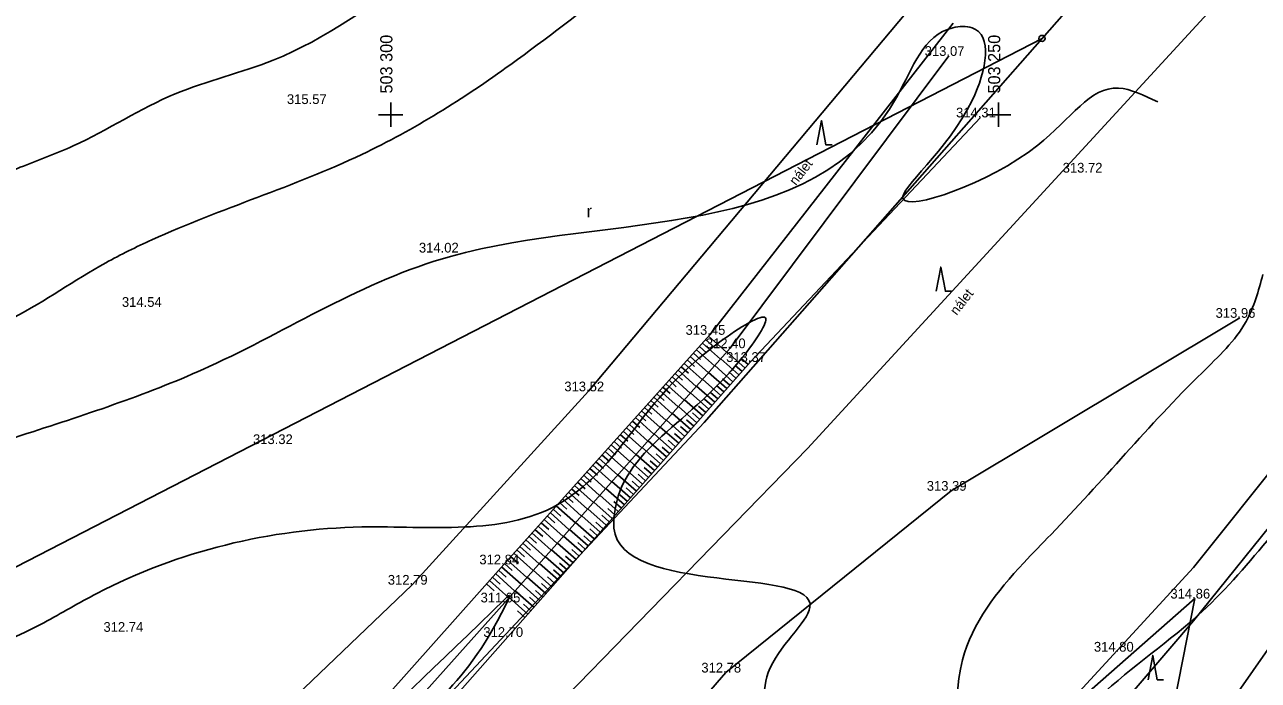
# Model space of a CAD drawing. Extents: x -504375 to -503125, y -1118000 to -1116474.
# Drawn here: x -503330.1 to -503228.6, y -1116596.5 to -1116542.6 of the extents above; entities that cross this region are included whole.
import ezdxf

# ---------------------------------------------------------------- set-up
doc = ezdxf.new("R2010")
doc.units = 0
for name, color, linetype in [('Druhy povrchů', 7, 'Continuous'), ('Podkladové mapy', 7, 'Continuous'), ('Vodní plochy', 7, 'Continuous'), ('Vrstva 34', 7, 'Continuous'), ('Vrstva 48', 7, 'Continuous'), ('Výškopis', 7, 'Continuous'), ('Výšky bodů plotr', 7, 'Continuous')]:
    doc.layers.add(name, color=color, linetype=linetype)

msp = doc.modelspace()

# ---------------------------------------------------------------- linework, layer by layer
at = {"layer": 'Druhy povrchů'}
for points in [[(-503397.02, -1116689.72), (-503380.03, -1116674.83), (-503363.8, -1116660.36), (-503349.88, -1116645.16), (-503336.27, -1116629.65), (-503324.3, -1116612.68), (-503313.46, -1116603.24), (-503298.24, -1116588.67), (-503283.72, -1116572.76), (-503255.76, -1116539.4)], [(-503264.953, -1116552.481), (-503264.578, -1116550.481), (-503264.203, -1116552.481), (-503263.703, -1116552.481)], [(-503255.127, -1116564.531), (-503254.752, -1116562.531), (-503254.377, -1116564.531), (-503253.877, -1116564.531)], [(-503585.68, -1116948.36), (-503569.03, -1116928.88), (-503555.79, -1116911.97), (-503526.22, -1116880.66), (-503498.19, -1116855.24), (-503492.29, -1116850.5), (-503465.52, -1116813.76), (-503435.92, -1116779.91), (-503416.58, -1116756.7), (-503397.18, -1116739.15), (-503383.4, -1116725.23), (-503367.95, -1116706.66), (-503351.89, -1116693.92), (-503339.03, -1116678.06), (-503323.29, -1116660.89), (-503310.81, -1116645.12), (-503295.5, -1116628.53), (-503285, -1116610.41), (-503272.45, -1116595.9), (-503253.91, -1116580.94), (-503230.15, -1116566.71)], [(-503237.698, -1116596.494), (-503237.323, -1116594.494), (-503236.948, -1116596.494), (-503236.448, -1116596.494)]]:
    msp.add_lwpolyline(points, dxfattribs=at)
at = {"layer": 'Podkladové mapy'}
for p, q in [((-503246.43, -1116543.72), (-503238.29, -1116534.46)), ((-503265.72, -1116577.46), (-503230.27, -1116538.88)), ((-503246.43, -1116543.72), (-503274.22, -1116575.33)), ((-503233.98, -1116587.25), (-503210.38, -1116557.71)), ((-503207.06, -1116558.21), (-503233.96, -1116591.65)), ((-503274.22, -1116575.33), (-503314.42, -1116618.21)), ((-503307.65, -1116620.55), (-503265.72, -1116577.46)), ((-503276.78, -1116633.82), (-503233.98, -1116587.25)), ((-503233.96, -1116591.65), (-503250.83, -1116611.29))]:
    msp.add_line(p, q, dxfattribs=at)
msp.add_lwpolyline([(-503572.98, -1116711.95), (-503406.03, -1116625.94), (-503246.43, -1116543.72)], dxfattribs=at)
for radius in [0.25, 0.005]:
    msp.add_circle((-503246.43, -1116543.72), radius, dxfattribs=at)
at = {"layer": 'Vodní plochy'}
for points in [[(-503272.08, -1116569.21), (-503254.08, -1116545.16)], [(-503290.61, -1116590.13), (-503272.08, -1116569.21)], [(-503334.47, -1116638.19), (-503314.17, -1116616.49), (-503290.61, -1116590.13)]]:
    msp.add_lwpolyline(points, dxfattribs=at)
at = {"layer": 'Vrstva 34'}
for p, q in [((-503300, -1116549), (-503300, -1116551)), ((-503250, -1116549), (-503250, -1116551)), ((-503299, -1116550), (-503301, -1116550)), ((-503249, -1116550), (-503251, -1116550))]:
    msp.add_line(p, q, dxfattribs=at)
at = {"layer": 'Vrstva 48'}
msp.add_lwpolyline([(-503300.434, -1116681.166), (-503296.556, -1116668.103), (-503294.8, -1116667.049), (-503286.048, -1116656.931), (-503285.304, -1116656.071), (-503279.91, -1116655.384), (-503275.719, -1116650.391), (-503271.777, -1116639.009), (-503265.04, -1116633.168), (-503262.143, -1116630.656), (-503250.15, -1116616.106), (-503234.98, -1116601.014), (-503231.273, -1116598.925), (-503211.098, -1116569.991), (-503210.256, -1116567.168)], dxfattribs=at)
for points in [[(-503290.496, -1116506.883), (-503309.393, -1116518.46), (-503328.29, -1116524.624), (-503350.268, -1116534.452), (-503366.085, -1116542.864), (-503383.317, -1116553.192), (-503389.867, -1116555.566), (-503411.101, -1116563.377)], [(-503423.262, -1116584.1), (-503400.51, -1116574.995), (-503371.603, -1116564.462), (-503355.454, -1116554.107), (-503339.126, -1116544.288), (-503329.669, -1116539.646), (-503315.72, -1116535.868), (-503281.172, -1116514.546)], [(-503272.713, -1116521.984), (-503284.552, -1116530.049), (-503297.613, -1116538.288), (-503309.659, -1116545.506), (-503317.719, -1116548.279), (-503326.116, -1116552.563), (-503330.483, -1116554.327), (-503334.009, -1116555.839), (-503347.343, -1116563.628), (-503356.881, -1116570.175), (-503363.037, -1116574.013), (-503376.976, -1116580.659), (-503385.521, -1116583.565), (-503391.321, -1116585.975), (-503395.157, -1116587.671), (-503409.879, -1116592.332), (-503411.663, -1116592.332), (-503418.533, -1116597.758), (-503431.06, -1116606.789)], [(-503388.833, -1116595.439), (-503375.375, -1116590.932), (-503361.776, -1116585.15), (-503355.232, -1116582.174), (-503340.443, -1116571.289), (-503331.009, -1116566.697), (-503323.444, -1116562.19), (-503319.644, -1116560.289), (-503302.365, -1116553.261), (-503290.126, -1116545.863), (-503272.293, -1116533.997), (-503262.721, -1116530.889)], [(-503465.065, -1116647.979), (-503454.005, -1116643.254), (-503444.995, -1116644.684), (-503441.273, -1116642.635), (-503427.473, -1116633.37), (-503425.422, -1116628.769), (-503418.525, -1116619.631), (-503414.99, -1116617.273), (-503410.82, -1116614.036), (-503399.7, -1116608.038), (-503368.713, -1116598.755), (-503365.041, -1116596.617), (-503349.145, -1116588.639), (-503333.919, -1116577.69), (-503329.925, -1116576.242), (-503314.946, -1116570.728), (-503295.077, -1116561.657), (-503258.316, -1116548.433), (-503253.777, -1116542.843), (-503252.181, -1116542.843), (-503252.181, -1116548.832), (-503257.867, -1116556.916), (-503246.784, -1116552.513), (-503240.14, -1116547.809), (-503236.915, -1116548.947)], [(-503228.261, -1116563.145), (-503229.645, -1116567.016), (-503233.265, -1116571.228), (-503245.688, -1116584.541), (-503247.935, -1116586.867), (-503252.973, -1116594.854), (-503254.135, -1116607.338), (-503261.55, -1116616.428), (-503262.857, -1116617.898), (-503273.652, -1116628.941), (-503288.12, -1116641.769), (-503294.834, -1116647.413), (-503299.542, -1116653.756), (-503302.433, -1116657.068), (-503311.897, -1116663.915), (-503313.227, -1116667.667), (-503316.736, -1116674.505), (-503325.627, -1116690.3), (-503328.511, -1116695.009), (-503335.94, -1116707.278), (-503351.034, -1116723.382), (-503365.126, -1116737.245), (-503372.674, -1116748.782), (-503373.925, -1116753.16), (-503378.551, -1116760.666), (-503382.552, -1116767.547), (-503390.579, -1116780.739), (-503398.79, -1116793.818), (-503400.908, -1116797.881), (-503402.495, -1116807.226), (-503404.198, -1116812.046), (-503412.471, -1116822.312), (-503418.387, -1116829.995), (-503420.024, -1116835.788), (-503425.814, -1116843.155), (-503430.336, -1116857.921), (-503433.683, -1116863.223), (-503434.674, -1116865.019), (-503440.926, -1116880.75), (-503445.259, -1116893.88)], [(-503481.504, -1116663.518), (-503468.547, -1116657.036), (-503463.489, -1116655.349), (-503455.413, -1116652.508), (-503447.337, -1116652.508), (-503443.352, -1116653.982), (-503430.298, -1116650.555), (-503416.187, -1116635.106), (-503410.685, -1116628.713), (-503402.504, -1116619.064), (-503381.737, -1116613.158), (-503370.807, -1116610.971), (-503361.189, -1116605.649), (-503353.61, -1116601.494), (-503341.223, -1116596.974), (-503328.544, -1116591.798), (-503324.172, -1116589.392), (-503302.385, -1116583.924), (-503293.932, -1116583.924), (-503286.266, -1116582.08), (-503284.637, -1116580.965), (-503272.933, -1116568.697), (-503269.17, -1116566.723), (-503271.089, -1116569.984), (-503281.636, -1116583.324), (-503281.636, -1116584.01), (-503265.516, -1116590.53), (-503268.945, -1116595.892), (-503268.945, -1116601.682), (-503275.976, -1116612.148), (-503282.064, -1116615.751), (-503283.352, -1116619.8), (-503288.876, -1116631.779), (-503303.377, -1116644.015), (-503307.12, -1116648.093), (-503316.743, -1116659.793), (-503321.087, -1116663.538), (-503326.965, -1116676.097), (-503331.52, -1116684.914), (-503334.134, -1116690.218), (-503342.049, -1116704.413), (-503355.564, -1116718.999), (-503373.009, -1116735.836), (-503382.317, -1116749.959), (-503386.693, -1116758.655), (-503400.779, -1116777.303), (-503409.619, -1116795.183), (-503415, -1116808.93), (-503418.611, -1116811.169), (-503424.106, -1116823.61), (-503426.69, -1116826.983), (-503429.797, -1116836.064), (-503433.946, -1116846.027), (-503439.043, -1116851.839), (-503444.852, -1116860.972), (-503445.916, -1116865.085), (-503449.799, -1116874.02), (-503458.366, -1116891.656), (-503466.054, -1116907.093), (-503467.087, -1116909.659), (-503470.52, -1116921.657)], [(-503220.996, -1116567.416), (-503217.756, -1116573.319), (-503221.427, -1116577.942), (-503233.269, -1116590.886), (-503241.732, -1116597.917), (-503258.62, -1116620.268), (-503262.643, -1116624.456), (-503264.199, -1116625.94)], [(-503500.793, -1116684.248), (-503495.441, -1116680.588), (-503477.217, -1116668.929), (-503469.765, -1116665.54), (-503456.961, -1116660.999), (-503454.929, -1116660.999), (-503445.173, -1116663.507), (-503440.16, -1116663.507), (-503423.051, -1116661.635), (-503408.15, -1116643.863), (-503398.378, -1116637.057), (-503392.648, -1116629.281), (-503371.711, -1116623.281), (-503344.722, -1116616.898), (-503335.508, -1116616.898), (-503327.111, -1116617.444), (-503318.26, -1116618.008), (-503315.381, -1116615.168), (-503290.617, -1116589.867), (-503290.243, -1116589.549), (-503290.538, -1116590.342), (-503300.683, -1116602.384), (-503312.519, -1116617.365), (-503317.698, -1116623.075), (-503317.198, -1116634.398), (-503334.088, -1116662.805), (-503335.757, -1116674.673), (-503338.13, -1116679.069), (-503344.017, -1116691.861), (-503347.356, -1116698.983), (-503360.449, -1116714.28), (-503364.755, -1116720.083), (-503377.404, -1116731.328), (-503383.122, -1116736.828), (-503390.673, -1116749.224), (-503402.769, -1116767.78), (-503415.526, -1116779.825), (-503422.011, -1116793.522), (-503432.295, -1116810.757), (-503433.452, -1116814.845), (-503436.422, -1116824.389), (-503442.016, -1116838.148), (-503445.44, -1116842.843), (-503455.651, -1116858.198), (-503457.49, -1116865.559), (-503458.811, -1116869.597), (-503464.787, -1116881.025), (-503469.417, -1116887.701), (-503473.366, -1116895.33), (-503475.204, -1116901.869), (-503476.43, -1116909.702), (-503479.902, -1116915.22), (-503480.991, -1116921.623), (-503488.414, -1116937.171)]]:
    msp.add_spline(points, degree=3, dxfattribs=at)
at = {"layer": 'Výškopis'}
for p, q in [((-503274.606, -1116569.064), (-503274.015, -1116569.595)), ((-503274.356, -1116568.785), (-503272.878, -1116570.111)), ((-503274.105, -1116568.506), (-503273.515, -1116569.036)), ((-503273.855, -1116568.227), (-503272.381, -1116569.55)), ((-503275.358, -1116569.901), (-503273.873, -1116571.234)), ((-503275.107, -1116569.622), (-503274.514, -1116570.154)), ((-503274.857, -1116569.343), (-503273.376, -1116570.673)), ((-503271.354, -1116571.409), (-503272.855, -1116570.085)), ((-503270.857, -1116570.847), (-503272.357, -1116569.523)), ((-503270.609, -1116570.566), (-503271.209, -1116570.036)), ((-503276.36, -1116571.017), (-503274.867, -1116572.357)), ((-503276.109, -1116570.738), (-503275.513, -1116571.273)), ((-503275.859, -1116570.459), (-503274.37, -1116571.795)), ((-503275.608, -1116570.18), (-503275.014, -1116570.714)), ((-503271.85, -1116571.972), (-503273.352, -1116570.646)), ((-503271.105, -1116571.128), (-503271.706, -1116570.599)), ((-503277.362, -1116572.133), (-503275.862, -1116573.48)), ((-503277.111, -1116571.854), (-503276.512, -1116572.392)), ((-503276.861, -1116571.575), (-503275.365, -1116572.918)), ((-503276.61, -1116571.296), (-503276.013, -1116571.833)), ((-503272.842, -1116573.096), (-503274.347, -1116571.769)), ((-503272.346, -1116572.534), (-503273.849, -1116571.207)), ((-503272.098, -1116572.253), (-503272.699, -1116571.722)), ((-503271.602, -1116571.69), (-503272.202, -1116571.16)), ((-503278.114, -1116572.97), (-503277.511, -1116573.511)), ((-503277.863, -1116572.691), (-503276.359, -1116574.041)), ((-503277.613, -1116572.412), (-503277.012, -1116572.951)), ((-503273.835, -1116574.221), (-503275.341, -1116572.892)), ((-503273.339, -1116573.659), (-503274.844, -1116572.33)), ((-503273.09, -1116573.378), (-503273.692, -1116572.846)), ((-503272.594, -1116572.815), (-503273.196, -1116572.284)), ((-503279.116, -1116574.086), (-503278.51, -1116574.63)), ((-503278.865, -1116573.807), (-503277.354, -1116575.164)), ((-503278.615, -1116573.528), (-503278.011, -1116574.07)), ((-503278.364, -1116573.249), (-503276.856, -1116574.603)), ((-503274.827, -1116575.346), (-503276.336, -1116574.015)), ((-503274.331, -1116574.783), (-503275.838, -1116573.453)), ((-503274.083, -1116574.502), (-503274.686, -1116573.97)), ((-503273.587, -1116573.94), (-503274.189, -1116573.408)), ((-503280.118, -1116575.202), (-503279.509, -1116575.748)), ((-503279.867, -1116574.923), (-503278.348, -1116576.287)), ((-503279.617, -1116574.644), (-503279.01, -1116575.189)), ((-503279.366, -1116574.365), (-503277.851, -1116575.726)), ((-503275.82, -1116576.47), (-503277.33, -1116575.138)), ((-503275.324, -1116575.908), (-503276.833, -1116574.576)), ((-503275.075, -1116575.627), (-503275.679, -1116575.094)), ((-503274.579, -1116575.065), (-503275.182, -1116574.532)), ((-503280.869, -1116576.04), (-503279.343, -1116577.41)), ((-503280.619, -1116575.76), (-503280.009, -1116576.308)), ((-503280.368, -1116575.481), (-503278.846, -1116576.848)), ((-503276.316, -1116577.033), (-503277.827, -1116575.699)), ((-503276.068, -1116576.752), (-503276.672, -1116576.218)), ((-503275.572, -1116576.189), (-503276.176, -1116575.656)), ((-503281.871, -1116577.156), (-503280.338, -1116578.533)), ((-503281.621, -1116576.877), (-503281.008, -1116577.427)), ((-503281.37, -1116576.598), (-503279.841, -1116577.972)), ((-503281.12, -1116576.319), (-503280.509, -1116576.867)), ((-503277.309, -1116578.157), (-503278.822, -1116576.822)), ((-503276.812, -1116577.595), (-503278.325, -1116576.261)), ((-503276.564, -1116577.314), (-503277.169, -1116576.78)), ((-503282.623, -1116577.993), (-503282.007, -1116578.546)), ((-503282.373, -1116577.714), (-503280.835, -1116579.094)), ((-503282.122, -1116577.435), (-503281.508, -1116577.986)), ((-503278.301, -1116579.282), (-503279.817, -1116577.945)), ((-503277.805, -1116578.72), (-503279.319, -1116577.383)), ((-503277.557, -1116578.439), (-503278.162, -1116577.904)), ((-503277.06, -1116577.876), (-503277.666, -1116577.342)), ((-503283.625, -1116579.109), (-503283.006, -1116579.664)), ((-503283.375, -1116578.83), (-503281.83, -1116580.217)), ((-503283.124, -1116578.551), (-503282.507, -1116579.105)), ((-503282.874, -1116578.272), (-503281.332, -1116579.656)), ((-503279.294, -1116580.407), (-503280.811, -1116579.067)), ((-503278.797, -1116579.845), (-503280.314, -1116578.506)), ((-503278.549, -1116579.563), (-503279.156, -1116579.028)), ((-503278.053, -1116579.001), (-503278.659, -1116578.466)), ((-503284.627, -1116580.225), (-503284.006, -1116580.783)), ((-503284.377, -1116579.946), (-503282.824, -1116581.34)), ((-503284.126, -1116579.667), (-503283.506, -1116580.224)), ((-503283.876, -1116579.388), (-503282.327, -1116580.778)), ((-503280.286, -1116581.532), (-503281.806, -1116580.19)), ((-503279.79, -1116580.969), (-503281.309, -1116579.629)), ((-503279.542, -1116580.688), (-503280.149, -1116580.152)), ((-503279.045, -1116580.126), (-503279.652, -1116579.59)), ((-503285.379, -1116581.062), (-503283.819, -1116582.463)), ((-503285.128, -1116580.783), (-503284.505, -1116581.343)), ((-503284.878, -1116580.504), (-503283.321, -1116581.901)), ((-503280.782, -1116582.094), (-503282.303, -1116580.752)), ((-503280.534, -1116581.813), (-503281.142, -1116581.276)), ((-503280.038, -1116581.25), (-503280.646, -1116580.714)), ((-503286.381, -1116582.178), (-503284.813, -1116583.586)), ((-503286.13, -1116581.899), (-503285.504, -1116582.462)), ((-503285.88, -1116581.62), (-503284.316, -1116583.024)), ((-503285.629, -1116581.341), (-503285.005, -1116581.902)), ((-503281.775, -1116583.219), (-503283.298, -1116581.875)), ((-503281.279, -1116582.656), (-503282.801, -1116581.313)), ((-503281.03, -1116582.375), (-503281.639, -1116581.838)), ((-503287.383, -1116583.294), (-503285.808, -1116584.708)), ((-503287.133, -1116583.015), (-503286.503, -1116583.58)), ((-503286.882, -1116582.736), (-503285.31, -1116584.147)), ((-503286.631, -1116582.457), (-503286.004, -1116583.021)), ((-503282.767, -1116584.343), (-503284.293, -1116582.998)), ((-503282.271, -1116583.781), (-503283.795, -1116582.436)), ((-503282.023, -1116583.5), (-503282.632, -1116582.962)), ((-503281.527, -1116582.937), (-503282.136, -1116582.4)), ((-503288.135, -1116584.132), (-503287.502, -1116584.699)), ((-503287.884, -1116583.853), (-503286.305, -1116585.27)), ((-503287.634, -1116583.573), (-503287.003, -1116584.14)), ((-503283.76, -1116585.468), (-503285.287, -1116584.121)), ((-503283.264, -1116584.906), (-503284.79, -1116583.559)), ((-503283.015, -1116584.625), (-503283.626, -1116584.086)), ((-503282.519, -1116584.062), (-503283.129, -1116583.524)), ((-503289.137, -1116585.248), (-503288.501, -1116585.818)), ((-503288.886, -1116584.969), (-503287.3, -1116586.393)), ((-503288.636, -1116584.69), (-503288.002, -1116585.259)), ((-503288.385, -1116584.411), (-503286.803, -1116585.832)), ((-503284.752, -1116586.593), (-503286.282, -1116585.243)), ((-503284.256, -1116586.03), (-503285.784, -1116584.682)), ((-503284.008, -1116585.749), (-503284.619, -1116585.21)), ((-503283.512, -1116585.187), (-503284.122, -1116584.648)), ((-503290.139, -1116586.364), (-503289.501, -1116586.937)), ((-503289.888, -1116586.085), (-503288.295, -1116587.516)), ((-503289.638, -1116585.806), (-503289.001, -1116586.378)), ((-503289.387, -1116585.527), (-503287.797, -1116586.955)), ((-503285.745, -1116587.717), (-503287.276, -1116586.366)), ((-503285.249, -1116587.155), (-503286.779, -1116585.805)), ((-503285, -1116586.874), (-503285.612, -1116586.334)), ((-503284.504, -1116586.312), (-503285.116, -1116585.772)), ((-503290.889, -1116587.202), (-503289.282, -1116588.631)), ((-503290.64, -1116586.922), (-503290, -1116587.496)), ((-503290.389, -1116586.643), (-503288.792, -1116588.077)), ((-503286.241, -1116588.28), (-503287.773, -1116586.927)), ((-503285.497, -1116587.436), (-503286.109, -1116586.896)), ((-503291.886, -1116588.323), (-503290.277, -1116589.754)), ((-503291.637, -1116588.043), (-503290.993, -1116588.615)), ((-503291.388, -1116587.762), (-503289.779, -1116589.192)), ((-503291.139, -1116587.482), (-503290.495, -1116588.054)), ((-503287.234, -1116589.404), (-503288.768, -1116588.05)), ((-503286.737, -1116588.842), (-503288.271, -1116587.489)), ((-503286.489, -1116588.561), (-503287.102, -1116588.02)), ((-503285.993, -1116587.999), (-503286.606, -1116587.458)), ((-503292.135, -1116588.603), (-503291.491, -1116589.176)), ((-503288.226, -1116590.529), (-503289.763, -1116589.173)), ((-503287.73, -1116589.967), (-503289.265, -1116588.612)), ((-503287.482, -1116589.686), (-503288.096, -1116589.144)), ((-503286.985, -1116589.123), (-503287.599, -1116588.582)), ((-503288.722, -1116591.092), (-503290.26, -1116589.735)), ((-503288.474, -1116590.81), (-503289.089, -1116590.268)), ((-503287.978, -1116590.248), (-503288.592, -1116589.706)), ((-503288.97, -1116591.373), (-503289.586, -1116590.83))]:
    msp.add_line(p, q, dxfattribs=at)
for points in [[(-503435.08, -1116738.92), (-503402.35, -1116702.54), (-503382.34, -1116679.28), (-503360.51, -1116664.43), (-503336.02, -1116637.68), (-503315.61, -1116615.01), (-503290.71, -1116587), (-503273.75, -1116568.11), (-503253.74, -1116542.47)], [(-503433.61, -1116740.76), (-503402.27, -1116708.45), (-503381.4, -1116682.04), (-503359.12, -1116667.62), (-503333.53, -1116638.6), (-503312.15, -1116617.61), (-503290.38, -1116592.97), (-503270.41, -1116570.34), (-503251.5, -1116550.22)], [(-503279.77, -1116636.44), (-503274.71, -1116628.94), (-503262.39, -1116614.92), (-503233.87, -1116589.81)], [(-503235.85, -1116599.99), (-503233.87, -1116589.81)]]:
    msp.add_lwpolyline(points, dxfattribs=at)

# ---------------------------------------------------------------- texts
at = {"layer": 'Druhy povrchů'}
for p in [(-503266.674, -1116555.87), (-503253.447, -1116566.557)]:
    msp.add_text('nálet', height=0.8, rotation=52.03077, dxfattribs=at).set_placement(p)
msp.add_text('r', height=1, dxfattribs=at).set_placement((-503283.886, -1116558.431))
at = {"layer": 'Vrstva 34'}
for s, p in [('503 300', (-503299.863, -1116548.255)), ('503 250', (-503249.863, -1116548.255))]:
    msp.add_text(s, height=1, rotation=90, dxfattribs=at).set_placement(p)
at = {"layer": 'Výšky bodů plotr'}
for s, p in [('313.07 ', (-503256.08, -1116545.16)), ('315.57 ', (-503308.54, -1116549.12)), ('314.31 ', (-503253.5, -1116550.22)), ('313.72 ', (-503244.73, -1116554.76)), ('314.02 ', (-503297.68, -1116561.34)), ('314.54 ', (-503322.11, -1116565.81)), ('313.96 ', (-503232.15, -1116566.71)), ('313.45 ', (-503275.75, -1116568.11)), ('312.40 ', (-503274.08, -1116569.21)), ('313.37 ', (-503272.41, -1116570.34)), ('313.52 ', (-503285.72, -1116572.76)), ('313.32 ', (-503311.33, -1116577.1)), ('313.39 ', (-503255.91, -1116580.94)), ('312.84 ', (-503292.71, -1116587)), ('312.79 ', (-503300.24, -1116588.67)), ('311.95 ', (-503292.61, -1116590.13)), ('314.86 ', (-503235.87, -1116589.81)), ('312.74 ', (-503323.63, -1116592.55)), ('312.70 ', (-503292.38, -1116592.97)), ('314.80 ', (-503242.16, -1116594.18)), ('312.78 ', (-503274.45, -1116595.9))]:
    msp.add_text(s, height=0.8, dxfattribs=at).set_placement(p)

doc.saveas('drawing.dxf')
